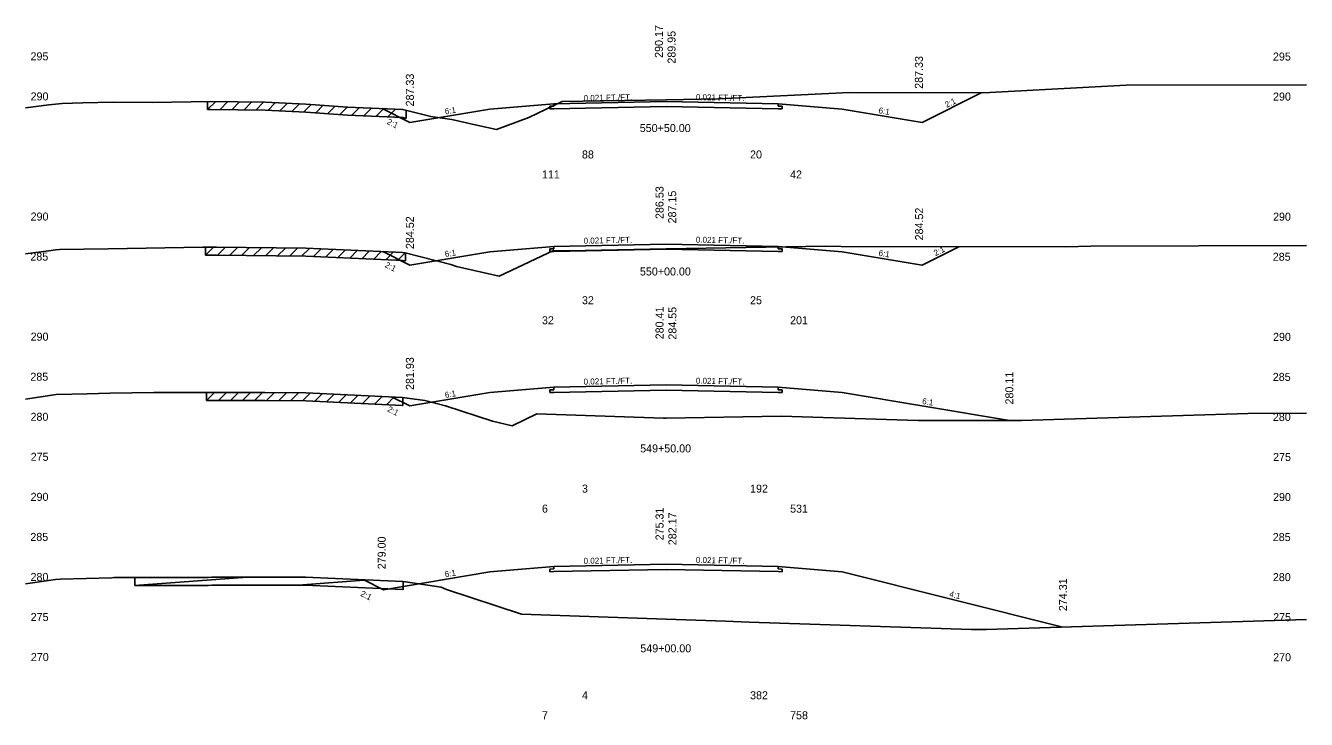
# Model space of a CAD drawing. Extents: x 2967 to 4323, y -3677 to -817.
# Drawn here: x 3555.3 to 3715.3, y -1602 to -1515.4 of the extents above; entities that cross this region are included whole.
import ezdxf

# ---------------------------------------------------------------- set-up
doc = ezdxf.new("R2010")
doc.units = 0
for name, color, linetype in [('Level 1', 7, 'Continuous'), ('Level 10', 7, 'Continuous'), ('Level 11', 7, 'Continuous'), ('Level 12', 7, 'Continuous'), ('Level 3', 7, 'Continuous'), ('Level 32', 7, 'Continuous'), ('Level 33', 7, 'Continuous'), ('Level 59', 7, 'Continuous'), ('Level 6', 7, 'Continuous'), ('Level 60', 7, 'Continuous'), ('Level 61', 7, 'Continuous'), ('Level 7', 7, 'Continuous')]:
    doc.layers.add(name, color=color, linetype=linetype)

msp = doc.modelspace()

# ---------------------------------------------------------------- linework, layer by layer
at = {"layer": 'Level 11'}
for p, q in [((3621.35, -1525.48), (3620.85, -1525.49)), ((3620.85, -1525.49), (3620.85, -1525.83)), ((3620.85, -1525.83), (3621.35, -1525.82)), ((3621.35, -1525.18), (3621.35, -1525.48)), ((3649.35, -1525.48), (3649.35, -1525.18)), ((3649.85, -1525.49), (3649.35, -1525.48)), ((3649.35, -1525.82), (3649.85, -1525.83)), ((3649.85, -1525.83), (3649.85, -1525.49)), ((3621.35, -1543.29), (3620.85, -1543.3)), ((3620.85, -1543.3), (3620.85, -1543.64)), ((3620.85, -1543.64), (3621.35, -1543.63)), ((3621.35, -1542.99), (3621.35, -1543.29)), ((3649.35, -1543.29), (3649.35, -1542.99)), ((3649.85, -1543.3), (3649.35, -1543.29)), ((3649.35, -1543.63), (3649.85, -1543.64)), ((3649.85, -1543.64), (3649.85, -1543.3)), ((3621.35, -1560.88), (3620.85, -1560.89)), ((3620.85, -1560.89), (3620.85, -1561.23)), ((3620.85, -1561.23), (3621.35, -1561.22)), ((3621.35, -1560.58), (3621.35, -1560.88)), ((3649.35, -1560.88), (3649.35, -1560.58)), ((3649.85, -1560.89), (3649.35, -1560.88)), ((3649.35, -1561.22), (3649.85, -1561.23)), ((3649.85, -1561.23), (3649.85, -1560.89)), ((3621.35, -1583.26), (3620.85, -1583.27)), ((3620.85, -1583.27), (3620.85, -1583.61)), ((3620.85, -1583.61), (3621.35, -1583.6)), ((3621.35, -1582.96), (3621.35, -1583.26)), ((3649.35, -1583.26), (3649.35, -1582.96)), ((3649.85, -1583.27), (3649.35, -1583.26)), ((3649.35, -1583.6), (3649.85, -1583.61)), ((3649.85, -1583.61), (3649.85, -1583.27))]:
    msp.add_line(p, q, dxfattribs=at)
at = {"layer": 'Level 12'}
for p, q in [((3635.35, -1525.53), (3621.35, -1525.82)), ((3649.35, -1525.82), (3635.35, -1525.53)), ((3635.35, -1543.34), (3621.35, -1543.63)), ((3649.35, -1543.63), (3635.35, -1543.34)), ((3635.35, -1560.93), (3621.35, -1561.22)), ((3649.35, -1561.22), (3635.35, -1560.93)), ((3635.35, -1583.31), (3621.35, -1583.6)), ((3649.35, -1583.6), (3635.35, -1583.31))]:
    msp.add_line(p, q, dxfattribs=at)
at = {"layer": 'Level 59'}
for p, q in [((3621.35, -1525.18), (3635.35, -1524.89)), ((3635.35, -1524.89), (3649.35, -1525.18)), ((3621.35, -1542.99), (3635.35, -1542.7)), ((3635.35, -1542.7), (3649.35, -1542.99)), ((3621.35, -1560.58), (3635.35, -1560.29)), ((3635.35, -1560.29), (3649.35, -1560.58)), ((3621.35, -1582.96), (3635.35, -1582.67)), ((3635.35, -1582.67), (3649.35, -1582.96))]:
    msp.add_line(p, q, dxfattribs=at)
at = {"layer": 'Level 6'}
for p, q in [((3613.35, -1525.85), (3621.35, -1525.18)), ((3649.35, -1525.18), (3657.35, -1525.85)), ((3613.35, -1543.65), (3621.35, -1542.99)), ((3649.35, -1542.99), (3657.35, -1543.65)), ((3613.35, -1561.25), (3621.35, -1560.58)), ((3649.35, -1560.58), (3657.35, -1561.25)), ((3613.35, -1583.63), (3621.35, -1582.96)), ((3649.35, -1582.96), (3657.35, -1583.63))]:
    msp.add_line(p, q, dxfattribs=at)
at = {"layer": 'Level 60'}
for p, q in [((3675.02, -1523.83), (3692.83, -1522.87)), ((3692.83, -1522.87), (3715.35, -1522.8)), ((3622.38, -1524.9), (3635.35, -1524.67)), ((3635.35, -1524.67), (3641.89, -1524.55)), ((3641.89, -1524.55), (3658.29, -1523.79)), ((3658.29, -1523.79), (3675.02, -1523.83)), ((3555.35, -1525.69), (3558.23, -1525.3)), ((3558.23, -1525.3), (3559.91, -1525.13)), ((3559.91, -1525.13), (3562.51, -1525.05)), ((3562.51, -1525.05), (3566.29, -1524.99)), ((3566.29, -1524.99), (3571.16, -1525.03)), ((3571.16, -1525.03), (3578.44, -1524.91)), ((3578.44, -1524.91), (3585.29, -1524.99)), ((3585.29, -1524.99), (3590.35, -1525.21)), ((3590.35, -1525.21), (3595.58, -1525.6)), ((3595.58, -1525.6), (3602.47, -1525.9)), ((3602.47, -1525.9), (3605.95, -1526.79)), ((3618.21, -1526.89), (3622.38, -1524.9)), ((3605.95, -1526.79), (3608.6, -1527.16)), ((3608.6, -1527.16), (3611.88, -1527.91)), ((3611.88, -1527.91), (3614.18, -1528.41)), ((3614.18, -1528.41), (3618.21, -1526.89)), ((3555.35, -1543.92), (3558.23, -1543.53)), ((3558.23, -1543.53), (3559.07, -1543.4)), ((3559.07, -1543.4), (3559.57, -1543.39)), ((3559.57, -1543.39), (3565.67, -1543.28)), ((3565.67, -1543.28), (3577.49, -1543.09)), ((3577.49, -1543.09), (3578.38, -1543.09)), ((3578.38, -1543.09), (3579.21, -1543.09)), ((3579.21, -1543.09), (3590.35, -1543.22)), ((3590.35, -1543.22), (3601.6, -1543.71)), ((3601.6, -1543.71), (3602.43, -1543.75)), ((3602.43, -1543.75), (3602.76, -1543.8)), ((3602.76, -1543.8), (3608.46, -1545.25)), ((3614.52, -1546.71), (3621.3, -1543.48)), ((3621.3, -1543.48), (3623.21, -1543.54)), ((3623.21, -1543.54), (3635.35, -1543.31)), ((3635.35, -1543.31), (3655.28, -1542.94)), ((3655.28, -1542.94), (3657.25, -1543)), ((3657.25, -1543), (3685.31, -1543.06)), ((3685.31, -1543.06), (3688.42, -1542.96)), ((3688.42, -1542.96), (3715.35, -1542.87)), ((3608.46, -1545.25), (3609.17, -1545.49)), ((3609.17, -1545.49), (3614.52, -1546.71)), ((3555.35, -1562.06), (3559.15, -1561.48)), ((3559.15, -1561.48), (3563.04, -1561.38)), ((3563.04, -1561.38), (3565.87, -1561.33)), ((3565.87, -1561.33), (3571.36, -1561.24)), ((3571.36, -1561.24), (3578.52, -1561.23)), ((3578.52, -1561.23), (3585.22, -1561.23)), ((3585.22, -1561.23), (3590.35, -1561.29)), ((3590.35, -1561.29), (3595.54, -1561.52)), ((3595.54, -1561.52), (3602.44, -1561.84)), ((3602.44, -1561.84), (3605.2, -1562.24)), ((3605.2, -1562.24), (3607.81, -1562.9)), ((3607.81, -1562.9), (3613.67, -1564.82)), ((3616.11, -1565.38), (3619.21, -1563.9)), ((3619.21, -1563.9), (3635.02, -1564.44)), ((3635.02, -1564.44), (3635.35, -1564.43)), ((3635.35, -1564.43), (3649.73, -1564.17)), ((3649.73, -1564.17), (3666.83, -1564.71)), ((3666.83, -1564.71), (3679.77, -1564.73)), ((3679.77, -1564.73), (3708.02, -1563.84)), ((3708.02, -1563.84), (3715.35, -1563.81)), ((3613.67, -1564.82), (3616.11, -1565.38)), ((3555.35, -1585.14), (3559.07, -1584.57)), ((3559.07, -1584.57), (3559.72, -1584.53)), ((3559.72, -1584.53), (3566.13, -1584.36)), ((3566.13, -1584.36), (3566.43, -1584.32)), ((3566.43, -1584.32), (3578.17, -1584.31)), ((3578.17, -1584.31), (3578.62, -1584.3)), ((3578.62, -1584.3), (3579.43, -1584.29)), ((3579.43, -1584.29), (3590.36, -1584.28)), ((3590.36, -1584.28), (3591.23, -1584.32)), ((3591.23, -1584.32), (3602.46, -1584.84)), ((3602.46, -1584.84), (3602.82, -1584.89)), ((3602.82, -1584.89), (3607.27, -1585.53)), ((3607.27, -1585.53), (3607.92, -1585.83)), ((3607.92, -1585.83), (3617.31, -1588.91)), ((3617.31, -1588.91), (3635.35, -1589.54)), ((3635.35, -1589.54), (3642.79, -1589.8)), ((3642.79, -1589.8), (3645.73, -1589.92)), ((3645.73, -1589.92), (3673.5, -1590.82)), ((3675.33, -1590.82), (3715.35, -1589.59)), ((3673.5, -1590.82), (3675.33, -1590.82))]:
    msp.add_line(p, q, dxfattribs=at)
at = {"layer": 'Level 61'}
for p, q in [((3579.09, -1524.91), (3578.09, -1525.91)), ((3578.09, -1524.91), (3578.09, -1525.91)), ((3578.09, -1525.91), (3578.44, -1525.91)), ((3578.44, -1525.91), (3585.29, -1525.99)), ((3580.58, -1524.93), (3579.59, -1525.92)), ((3582.08, -1524.95), (3581.09, -1525.94)), ((3583.58, -1524.97), (3582.59, -1525.96)), ((3585.08, -1524.99), (3584.09, -1525.97)), ((3585.29, -1525.99), (3590.35, -1526.21)), ((3586.55, -1525.04), (3585.59, -1526)), ((3588.05, -1525.11), (3587.09, -1526.07)), ((3589.55, -1525.18), (3588.59, -1526.13)), ((3591.03, -1525.26), (3590.09, -1526.2)), ((3590.35, -1526.21), (3595.58, -1526.6)), ((3592.52, -1525.37), (3591.59, -1526.3)), ((3594.02, -1525.48), (3593.09, -1526.41)), ((3595.52, -1525.6), (3594.59, -1526.53)), ((3597.05, -1525.66), (3596.09, -1526.62)), ((3598.55, -1525.73), (3597.59, -1526.69)), ((3600.05, -1525.8), (3599.09, -1526.75)), ((3601.55, -1525.86), (3600.59, -1526.82)), ((3602.88, -1527.01), (3602.88, -1526.01)), ((3595.58, -1526.6), (3602.47, -1526.9)), ((3602.47, -1526.9), (3602.88, -1527.01)), ((3578.83, -1543.09), (3577.83, -1544.09)), ((3577.83, -1543.09), (3577.83, -1544.09)), ((3580.31, -1543.1), (3579.33, -1544.09)), ((3581.81, -1543.12), (3580.83, -1544.11)), ((3583.31, -1543.14), (3582.33, -1544.13)), ((3584.81, -1543.16), (3583.83, -1544.14)), ((3586.31, -1543.17), (3585.33, -1544.16)), ((3587.81, -1543.19), (3586.83, -1544.18)), ((3589.31, -1543.21), (3588.33, -1544.2)), ((3590.8, -1543.24), (3589.83, -1544.22)), ((3592.28, -1543.31), (3591.33, -1544.26)), ((3593.78, -1543.37), (3592.83, -1544.33)), ((3595.28, -1543.44), (3594.33, -1544.4)), ((3596.78, -1543.5), (3595.83, -1544.46)), ((3598.28, -1543.57), (3597.33, -1544.53)), ((3599.78, -1543.63), (3598.83, -1544.59)), ((3601.28, -1543.7), (3600.33, -1544.66)), ((3602.75, -1543.8), (3601.83, -1544.72)), ((3602.79, -1544.81), (3602.79, -1543.81)), ((3577.83, -1544.09), (3578.38, -1544.09)), ((3578.38, -1544.09), (3579.21, -1544.09)), ((3579.21, -1544.09), (3590.35, -1544.22)), ((3590.35, -1544.22), (3601.6, -1544.71)), ((3601.6, -1544.71), (3602.43, -1544.75)), ((3602.43, -1544.75), (3602.76, -1544.8)), ((3602.76, -1544.8), (3602.79, -1544.81)), ((3578.94, -1561.23), (3577.94, -1562.23)), ((3577.94, -1561.23), (3577.94, -1562.23)), ((3580.44, -1561.23), (3579.44, -1562.23)), ((3581.94, -1561.23), (3580.94, -1562.23)), ((3583.44, -1561.23), (3582.44, -1562.23)), ((3584.94, -1561.23), (3583.94, -1562.23)), ((3586.43, -1561.25), (3585.44, -1562.23)), ((3587.93, -1561.26), (3586.94, -1562.25)), ((3589.43, -1561.28), (3588.44, -1562.27)), ((3590.91, -1561.32), (3589.94, -1562.29)), ((3592.4, -1561.38), (3591.44, -1562.34)), ((3593.9, -1561.45), (3592.94, -1562.41)), ((3595.4, -1561.51), (3594.44, -1562.47)), ((3596.9, -1561.58), (3595.94, -1562.54)), ((3577.94, -1562.23), (3578.52, -1562.23)), ((3578.52, -1562.23), (3585.22, -1562.23)), ((3585.22, -1562.23), (3590.35, -1562.29)), ((3590.35, -1562.29), (3595.54, -1562.52)), ((3595.54, -1562.52), (3602.44, -1562.84)), ((3598.4, -1561.65), (3597.44, -1562.61)), ((3599.9, -1561.72), (3598.94, -1562.68)), ((3601.4, -1561.79), (3600.44, -1562.75)), ((3602.44, -1562.84), (3602.46, -1562.84)), ((3602.46, -1562.84), (3602.46, -1561.84)), ((3583.01, -1584.29), (3569.01, -1585.32)), ((3569.01, -1584.32), (3569.01, -1585.32)), ((3569.01, -1585.32), (3578.17, -1585.31)), ((3578.17, -1585.31), (3578.62, -1585.3)), ((3578.62, -1585.3), (3579.43, -1585.29)), ((3579.43, -1585.29), (3590.36, -1585.28)), ((3598.16, -1584.64), (3589.43, -1585.28)), ((3590.36, -1585.28), (3591.23, -1585.32)), ((3591.23, -1585.32), (3602.46, -1585.84)), ((3602.5, -1585.85), (3602.5, -1584.85)), ((3602.46, -1585.84), (3602.5, -1585.85))]:
    msp.add_line(p, q, dxfattribs=at)
at = {"layer": 'Level 7'}
for p, q in [((3667.35, -1527.51), (3674.71, -1523.83)), ((3599.9, -1525.79), (3603.35, -1527.51)), ((3603.35, -1527.51), (3613.35, -1525.85)), ((3657.35, -1525.85), (3667.35, -1527.51)), ((3599.99, -1543.64), (3603.35, -1545.32)), ((3603.35, -1545.32), (3613.35, -1543.65)), ((3657.35, -1543.65), (3667.35, -1545.32)), ((3667.35, -1545.32), (3671.93, -1543.03)), ((3603.35, -1562.91), (3613.35, -1561.25)), ((3657.35, -1561.25), (3678.24, -1564.73)), ((3601.07, -1561.78), (3603.35, -1562.91)), ((3600.05, -1585.85), (3613.35, -1583.63)), ((3657.35, -1583.63), (3684.94, -1590.53)), ((3597.59, -1584.62), (3600.05, -1585.85))]:
    msp.add_line(p, q, dxfattribs=at)

# ---------------------------------------------------------------- texts
at = {"layer": 'Level 1'}
for s, p in [('88', (3624.85, -1532.01)), ('20', (3645.85, -1532.01)), ('111', (3619.85, -1534.51)), ('42', (3650.85, -1534.51)), ('32', (3624.85, -1550.21)), ('25', (3645.85, -1550.21)), ('32', (3619.85, -1552.71)), ('201', (3650.85, -1552.71)), ('3', (3624.85, -1573.73)), ('192', (3645.85, -1573.73)), ('6', (3619.85, -1576.23)), ('531', (3650.85, -1576.23)), ('4', (3624.85, -1599.53)), ('382', (3645.85, -1599.53)), ('7', (3619.85, -1602.03)), ('758', (3650.85, -1602.03))]:
    msp.add_text(s, height=1, dxfattribs=at).set_placement(p)
at = {"layer": 'Level 10'}
for s, p in [('290.17', (3634.96, -1519.45)), ('286.53', (3635.04, -1539.57)), ('280.41', (3635.04, -1554.59)), ('275.31', (3635.04, -1579.69))]:
    msp.add_text(s, height=1, rotation=90, dxfattribs=at).set_placement(p)
for s, p in [('550+50.00', (3632.07, -1528.71)), ('550+00.00', (3632.09, -1546.62)), ('549+50.00', (3632.12, -1568.71)), ('549+00.00', (3632.14, -1593.67))]:
    msp.add_text(s, height=1, dxfattribs=at).set_placement(p)
at = {"layer": 'Level 3'}
for s, p in [(' 295', (3555.59, -1519.76)), (' 295', (3710.8, -1519.78)), (' 290', (3555.6, -1524.76)), (' 290', (3710.81, -1524.78)), (' 290', (3555.6, -1539.76)), (' 290', (3710.81, -1539.78)), (' 285', (3555.57, -1544.76)), (' 285', (3710.78, -1544.78)), (' 290', (3555.6, -1554.76)), (' 290', (3710.81, -1554.78)), (' 285', (3555.57, -1559.76)), (' 285', (3710.78, -1559.78)), (' 280', (3555.59, -1564.76)), (' 280', (3710.79, -1564.78)), (' 275', (3555.61, -1569.76)), (' 275', (3710.82, -1569.78)), (' 290', (3555.6, -1574.76)), (' 290', (3710.81, -1574.78)), (' 285', (3555.57, -1579.76)), (' 285', (3710.78, -1579.78)), (' 280', (3555.59, -1584.76)), (' 280', (3710.79, -1584.78)), (' 275', (3555.61, -1589.76)), (' 275', (3710.82, -1589.78)), (' 270', (3555.63, -1594.76)), (' 270', (3710.83, -1594.78))]:
    msp.add_text(s, height=1, dxfattribs=at).set_placement(p)
at = {"layer": 'Level 32'}
for s, rotation, p in [('0.021 FT./FT.', 1.1916, (3625.06, -1524.85)), ('0.021 FT./FT.', 358.8084, (3639.07, -1524.72)), ('2:1', 26.5651, (3670.41, -1525.7)), ('6:1', 9.4623, (3607.78, -1526.52)), ('6:1', 350.5377, (3661.86, -1526.35)), ('2:1', 333.435, (3600.41, -1527.67)), ('0.021 FT./FT.', 1.1916, (3625.06, -1542.66)), ('0.021 FT./FT.', 358.8084, (3639.07, -1542.52)), ('6:1', 9.4623, (3607.78, -1544.33)), ('6:1', 350.5377, (3661.86, -1544.15)), ('2:1', 26.5651, (3669.02, -1544.21)), ('2:1', 333.435, (3600.16, -1545.54)), ('0.021 FT./FT.', 1.1916, (3625.06, -1560.25)), ('0.021 FT./FT.', 358.8084, (3639.07, -1560.12)), ('6:1', 9.4623, (3607.78, -1561.92)), ('2:1', 333.435, (3600.47, -1563.55)), ('6:1', 350.5377, (3667.31, -1562.65)), ('0.021 FT./FT.', 1.1916, (3625.06, -1582.63)), ('0.021 FT./FT.', 358.8084, (3639.07, -1582.5)), ('6:1', 9.4623, (3607.78, -1584.3)), ('2:1', 333.435, (3597.1, -1586.58)), ('4:1', 345.9638, (3670.69, -1586.71))]:
    msp.add_text(s, height=0.75, rotation=rotation, dxfattribs=at).set_placement(p)
at = {"layer": 'Level 33'}
for s, p in [('287.33', (3667.44, -1523.31)), ('287.33', (3603.85, -1525.51)), ('284.52', (3667.47, -1542.24)), ('284.52', (3603.85, -1543.32)), ('281.93', (3603.85, -1560.91)), ('280.11', (3678.74, -1562.73)), ('279.00', (3600.33, -1583.3)), ('274.31', (3685.44, -1588.53))]:
    msp.add_text(s, height=1, rotation=90, dxfattribs=at).set_placement(p)
at = {"layer": 'Level 59'}
for s, p in [(' 289.95', (3636.54, -1520.54)), (' 287.15', (3636.62, -1540.49)), ('284.55', (3636.65, -1554.63)), (' 282.17', (3636.65, -1580.67))]:
    msp.add_text(s, height=1, rotation=90, dxfattribs=at).set_placement(p)

doc.saveas('drawing.dxf')
